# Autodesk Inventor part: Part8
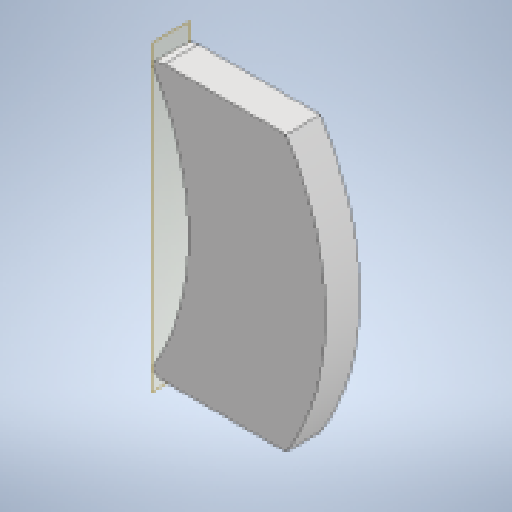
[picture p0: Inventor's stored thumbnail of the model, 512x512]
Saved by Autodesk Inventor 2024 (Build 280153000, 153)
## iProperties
Created: 2024-05
Part Number: Part8
Material: Generic
Document SubType Name: Modeling
Designer: dylan
Density: 1 g/cm^3
Appearance: Default
Author: dylan
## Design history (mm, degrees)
sketch "Sketch1"
  geometry: L1 (0, 0)-(-10, 0); L2 (-53.17, 58.792)-(-33.17, 24.151) reference; L3 (-41.83, 19.151)-(-61.83, 53.792) reference; L4 (0, 5)-(40, 5) reference; L5 (40, -5)-(0, -5) reference; L6 (-33.17, -24.151)-(-53.17, -58.792) reference; L7 (-61.83, -53.792)-(-41.83, -19.151) reference; L8 (-10, -23.526)-(-10, 0); L9 (3.114, -40)-(38.62, -40); L10 (-10, -25.115)-(11.051, -25.115); L11 (-9.082, -26.412)-(-0.969, -37.887); L12 (-10, 23.526)-(-10, 0); L13 (-9.082, 26.412)-(-0.969, 37.887); L14 (3.114, 40)-(38.62, 40); L15 (-4.416, 44.347)-(-22.169, 75.097); L16 (-10.085, 26.991)-(-4.205, 39.755); L17 (-12.126, 24.753)-(-32.5, 12.99); L18 (-10.75, 25.548)-(-21.275, 43.778); L19 (-52.874, 1.228)-(-32.5, 12.99); L20 (-55.832, 0.579)-(-69.826, 1.868); L21 (-73.698, 4.347)-(-91.451, 35.097); L22 (-73.698, -4.347)-(-91.451, -35.097); L23 (-55.832, -0.579)-(-69.826, -1.868); L24 (-52.874, -1.228)-(-32.5, -12.99); L25 (-54.25, -0.433)-(-64.775, -18.664); L26 (-12.126, -24.753)-(-32.5, -12.99); L27 (-10.085, -26.991)-(-4.205, -39.755); L28 (-4.416, -44.347)-(-22.169, -75.097); C1 r 2.5 at (-25, 0) reference; C2 r 4.75 at (0, 0) reference; C3 r 4.75 at (0, 0); A1 r 5 centre (-57.5, 56.292) between (-53.17, 58.792) and (-61.83, 53.792) reference; A2 r 5 centre (-37.5, 21.651) between (-41.83, 19.151) and (-33.17, 24.151) reference; A3 r 5 centre (40, 0) between (40, -5) and (40, 5) reference; A4 r 5 centre (0, 0) between (0, 5) and (0, -5) reference; A5 r 5 centre (-57.5, -56.292) between (-61.83, -53.792) and (-53.17, -58.792) reference; A6 r 5 centre (-37.5, -21.651) between (-33.17, -24.151) and (-41.83, -19.151) reference; A7 r 75.15 centre (-25, 0) between (38.62, -40) and (38.62, 40); A8 r 75.15 centre (-25, 0) between (-21.485, 75.068) and (-91.451, -35.097); A9 r 75.15 centre (-25, 0) between (-22.169, -75.097) and (-20.093, -74.99); A10 r 5 centre (3.114, -35) between (-0.969, -37.887) and (3.114, -40); A11 r 5 centre (-5, -23.526) between (-10, -23.526) and (-9.082, -26.412); A12 r 5 centre (-5, 23.526) between (-9.082, 26.412) and (-10, 23.526); A13 r 5 centre (3.114, 35) between (3.114, 40) and (-0.969, 37.887); A14 r 5 centre (-8.746, 41.847) between (-4.205, 39.755) and (-4.416, 44.347); A15 r 5 centre (-14.626, 29.083) between (-12.126, 24.753) and (-10.085, 26.991); A16 r 5 centre (-55.374, 5.558) between (-55.832, 0.579) and (-52.874, 1.228); A17 r 5 centre (-69.368, 6.847) between (-73.698, 4.347) and (-69.826, 1.868); A18 r 5 centre (-69.368, -6.847) between (-69.826, -1.868) and (-73.698, -4.347); A19 r 5 centre (-55.374, -5.558) between (-52.874, -1.228) and (-55.832, -0.579); A20 r 5 centre (-14.626, -29.083) between (-10.085, -26.991) and (-12.126, -24.753); A21 r 5 centre (-8.746, -41.847) between (-4.416, -44.347) and (-4.205, -39.755); 9 further points
  constraints: 44 end point, 30 point on circle, 24 point on line, 16 centre point, 8 tangent, 4 equal radius, 2 horizontal, 2 symmetric about line, 1 coincident, 1 perpendicular, 94 other
  dimensions: "d1" = 10 distance of L1.start L1.end; "d16" = 25.11474 distance of L10.start L1.end; "d29" = 5 radius of A10; "d32" = 360 deg dimension on A7.centre L9.start (derived)
extrude "Extrusion1" new body sketch "Sketch1" distance "d12" = 10; taper "d13" = 0 deg
sketch "Sketch4"
  geometry: 1 further point
body "Solid1"
node "Reference2"
